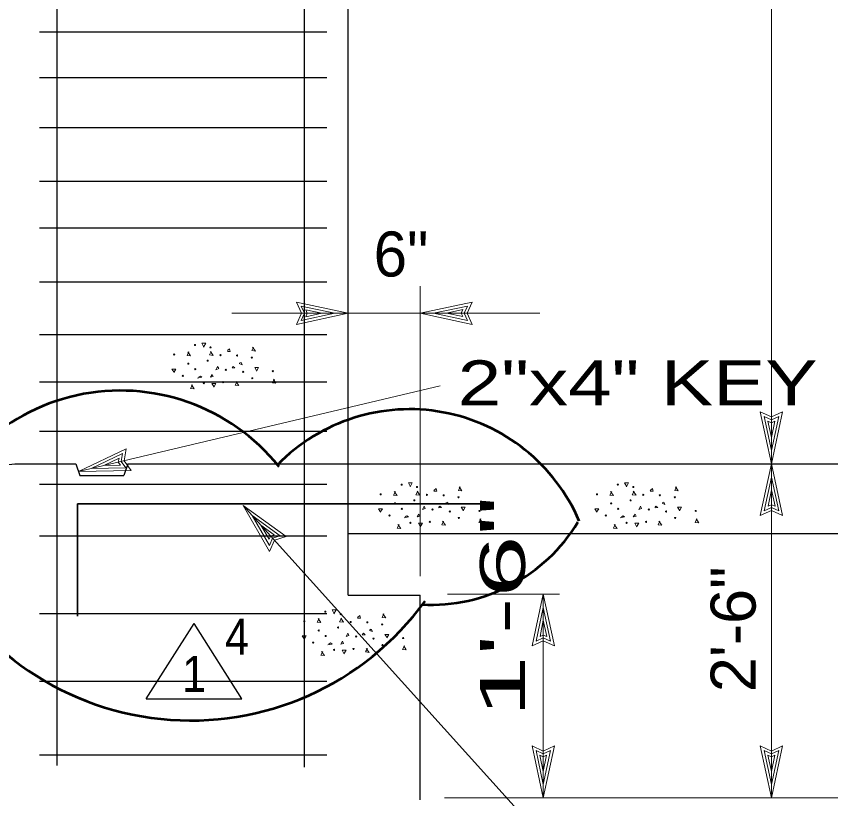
# Model space of a CAD drawing. Extents: x -28.1 to 13.9, y -16.1 to 13.9.
# Drawn here: x -2.228 to 0.036, y 3.076 to 5.249 of the extents above; entities that cross this region are included whole.
import ezdxf
from ezdxf.enums import TextEntityAlignment as Align

# ---------------------------------------------------------------- set-up
doc = ezdxf.new("R2010")
doc.units = 0
doc.header["$LTSCALE"] = 0.05
doc.layers.add('1', color=7, linetype='Continuous', lineweight=13)
doc.layers.add('2', color=7, linetype='Continuous', lineweight=13)

msp = doc.modelspace()

# ---------------------------------------------------------------- linework, layer by layer
at = {"layer": '1', "lineweight": 25}
for p, q in [((-1.30504, 3.64169), (-1.30504, 10.57569)), ((-1.42704, 3.16369), (-1.42704, 10.52469)), ((-2.11404, 3.16869), (-2.11404, 10.51569)), ((-2.16304, 5.20669), (-1.36504, 5.20669)), ((-2.16304, 5.07969), (-1.36504, 5.07969)), ((-2.16304, 4.94069), (-1.36504, 4.94069)), ((-2.16304, 4.79169), (-1.36504, 4.79169)), ((-2.16304, 4.66169), (-1.36504, 4.66169)), ((-2.16304, 4.51169), (-1.36504, 4.51169)), ((-2.16304, 4.36569), (-1.36504, 4.36569)), ((-2.16304, 4.23369), (-1.36504, 4.23369)), ((-2.16304, 4.09669), (-1.36504, 4.09669)), ((-2.06204, 4.00669), (-2.05104, 3.97369)), ((-1.91804, 4.00669), (-1.92904, 3.97369)), ((-1.91804, 4.00669), (0.45096, 4.00669)), ((-2.05104, 3.97369), (-1.92904, 3.97369)), ((-2.16304, 3.94969), (-1.36504, 3.94969)), ((-2.16304, 3.80669), (-1.36504, 3.80669)), ((-1.30504, 3.81269), (0.45596, 3.81269)), ((-1.30504, 3.64169), (-1.10504, 3.64169)), ((-1.10504, 3.07269), (-1.10504, 3.64169)), ((-2.16304, 3.59069), (-1.36504, 3.59069)), ((-1.86643, 3.35403), (-1.73343, 3.56303)), ((-1.60043, 3.35403), (-1.73343, 3.56303)), ((-2.16304, 3.40269), (-1.36504, 3.40269)), ((-1.86643, 3.35403), (-1.60043, 3.35403)), ((-2.16304, 3.19769), (-1.36504, 3.19769))]:
    msp.add_line(p, q, dxfattribs=at)
at = {"layer": '1'}
for p, q in [((-1.10504, 3.69469), (-1.10504, 4.49969)), ((-1.30504, 4.42469), (-1.44904, 4.45569)), ((-1.34204, 4.42469), (-1.43604, 4.44469)), ((-1.42704, 4.42469), (-1.43604, 4.44469)), ((-1.10504, 4.42469), (-0.96104, 4.45569)), ((-1.06804, 4.42469), (-0.97404, 4.44469)), ((-0.97404, 4.44469), (-0.98304, 4.42469)), ((-1.30504, 4.42469), (-1.44904, 4.39369)), ((-1.34204, 4.42469), (-1.43604, 4.40469)), ((-1.43604, 4.40469), (-1.42704, 4.42469)), ((-1.37804, 4.42469), (-1.42304, 4.43369)), ((-1.41904, 4.42469), (-1.42304, 4.43369)), ((-1.37804, 4.42469), (-1.42304, 4.41469)), ((-1.42304, 4.41469), (-1.41904, 4.42469)), ((-1.10504, 4.42469), (-0.96104, 4.39369)), ((-1.06804, 4.42469), (-0.97404, 4.40469)), ((-1.03204, 4.42469), (-0.98704, 4.43469)), ((-1.03204, 4.42469), (-0.98704, 4.41569)), ((-0.98704, 4.43469), (-0.99104, 4.42469)), ((-0.99104, 4.42469), (-0.98704, 4.41569)), ((-0.98304, 4.42469), (-0.97404, 4.40469)), ((-2.05504, 3.98469), (-1.05004, 4.22269)), ((-0.12904, 4.00669), (-0.16004, 4.15069)), ((-0.12904, 4.00669), (-0.09804, 4.15069)), ((-0.12904, 4.04369), (-0.14904, 4.13769)), ((-0.14904, 4.13769), (-0.12904, 4.12869)), ((-0.12904, 4.07969), (-0.13904, 4.12469)), ((-0.13904, 4.12469), (-0.12904, 4.12069)), ((-0.12904, 4.04369), (-0.10904, 4.13769)), ((-0.12904, 4.12869), (-0.10904, 4.13769)), ((-0.12904, 4.07969), (-0.12004, 4.12469)), ((-0.12904, 4.12069), (-0.12004, 4.12469)), ((-2.05504, 3.98469), (-1.92204, 4.04769)), ((-2.01904, 3.99369), (-1.93204, 4.03469)), ((-1.93204, 4.03469), (-1.93604, 4.01269)), ((-1.98404, 4.00169), (-1.94204, 4.02169)), ((-1.94204, 4.02169), (-1.94404, 4.01069)), ((-1.94404, 4.01069), (-1.93804, 4.00269)), ((-1.93604, 4.01269), (-1.92304, 3.99569)), ((-0.12904, 4.00669), (-0.16004, 3.86269)), ((-0.12904, 4.00669), (-0.09804, 3.86269)), ((-2.05504, 3.98469), (-1.90804, 3.98769)), ((-2.01904, 3.99369), (-1.92304, 3.99569)), ((-1.98404, 4.00169), (-1.93804, 4.00269)), ((-0.12904, 3.96969), (-0.14904, 3.87569)), ((-0.12904, 3.96969), (-0.10904, 3.87569)), ((-0.12904, 3.93369), (-0.13804, 3.88869)), ((-0.12904, 3.93369), (-0.11904, 3.88869)), ((-0.12904, 3.89269), (-0.13804, 3.88869)), ((-0.11904, 3.88869), (-0.12904, 3.89269)), ((-1.59712, 3.89047), (-1.47767, 3.80428)), ((-1.59712, 3.89047), (-1.52372, 3.76277)), ((-0.12904, 3.88469), (-0.14904, 3.87569)), ((-0.10904, 3.87569), (-0.12904, 3.88469)), ((-1.57234, 3.86299), (-1.49454, 3.80657)), ((-1.57234, 3.86299), (-1.52425, 3.77979)), ((-1.54824, 3.83625), (-1.52479, 3.79681)), ((-1.54824, 3.83625), (-1.51068, 3.80953)), ((-1.52078, 3.8058), (-1.52479, 3.79681)), ((-1.51068, 3.80953), (-1.52078, 3.8058)), ((-1.49454, 3.80657), (-1.51543, 3.79986)), ((-1.51543, 3.79986), (-1.52425, 3.77979)), ((-1.02904, 3.64469), (-0.71804, 3.64469)), ((-0.76304, 3.64469), (-0.79404, 3.50069)), ((-0.76304, 3.07869), (-0.76304, 3.64469)), ((-0.76304, 3.64469), (-0.73204, 3.50069)), ((-0.76304, 3.60769), (-0.78304, 3.51369)), ((-0.76304, 3.60769), (-0.74304, 3.51369)), ((-0.76304, 3.57169), (-0.77204, 3.52669)), ((-0.76304, 3.57169), (-0.75304, 3.52669)), ((-0.76304, 3.53069), (-0.77204, 3.52669)), ((-0.75304, 3.52669), (-0.76304, 3.53069)), ((-0.76304, 3.52269), (-0.78304, 3.51369)), ((-0.74304, 3.51369), (-0.76304, 3.52269)), ((-0.76304, 3.07869), (-0.79404, 3.22269)), ((-0.76304, 3.07869), (-0.73204, 3.22269)), ((-0.12904, 3.07869), (-0.16004, 3.22269)), ((-0.12904, 3.07869), (-0.09804, 3.22269)), ((-0.76304, 3.11569), (-0.78304, 3.20969)), ((-0.78304, 3.20969), (-0.76304, 3.20069)), ((-0.76304, 3.15169), (-0.77304, 3.19669)), ((-0.77304, 3.19669), (-0.76304, 3.19269)), ((-0.76304, 3.11569), (-0.74304, 3.20969)), ((-0.76304, 3.20069), (-0.74304, 3.20969)), ((-0.76304, 3.15169), (-0.75404, 3.19669)), ((-0.76304, 3.19269), (-0.75404, 3.19669)), ((-0.12904, 3.11569), (-0.14904, 3.20969)), ((-0.14904, 3.20969), (-0.12904, 3.20069)), ((-0.12904, 3.15169), (-0.13904, 3.19669)), ((-0.13904, 3.19669), (-0.12904, 3.19269)), ((-0.12904, 3.11569), (-0.10904, 3.20969)), ((-0.12904, 3.20069), (-0.10904, 3.20969)), ((-0.12904, 3.15169), (-0.12004, 3.19669)), ((-0.12904, 3.19269), (-0.12004, 3.19669)), ((-1.03804, 3.07869), (0.37996, 3.07869))]:
    msp.add_line(p, q, dxfattribs=at)
at = {"layer": '1', "lineweight": 35}
for q in [(-0.90956, 3.89565), (-2.05726, 3.58294)]:
    msp.add_line((-2.05726, 3.89565), q, dxfattribs=at)
at = {"layer": '1'}
for points in [[(-0.12904, 3.07869), (-0.12904, 4.00669), (-0.12904, 10.57569)], [(-1.44904, 4.39369), (-1.43504, 4.42469), (-1.44904, 4.45569)], [(-0.96104, 4.45569), (-0.97504, 4.42469), (-0.96104, 4.39369)], [(-1.62904, 4.42469), (-1.30504, 4.42469), (-1.10504, 4.42469), (-0.77304, 4.42469)], [(-0.16004, 4.15069), (-0.12904, 4.13669), (-0.09804, 4.15069)], [(-1.92204, 4.04769), (-1.92804, 4.01469), (-1.90804, 3.98769)], [(-1.59712, 3.89047), (-0.28558, 2.43598), (0.38318, 2.43322)], [(-0.09804, 3.86269), (-0.12904, 3.87669), (-0.16004, 3.86269)], [(-1.47767, 3.80428), (-1.51007, 3.79393), (-1.52372, 3.76277)], [(-0.73204, 3.50069), (-0.76304, 3.51469), (-0.79404, 3.50069)], [(-0.79404, 3.22269), (-0.76304, 3.20869), (-0.73204, 3.22269)], [(-0.16004, 3.22269), (-0.12904, 3.20869), (-0.09804, 3.22269)]]:
    msp.add_lwpolyline(points, dxfattribs=at)
at = {"layer": '1', "lineweight": 25}
msp.add_lwpolyline([(-2.61504, 3.96269), (-2.23204, 4.00669), (-2.06204, 4.00669)], dxfattribs=at)
at = {"layer": '1', "lineweight": 53}
for centre, radius, start, end in [((-1.93793, 3.64507), 0.56467, 38.72638, 166.28242), ((-1.13461, 3.64489), 0.51309, 23.23358, 135.73917), ((-1.07443, 4.09144), 0.47656, 266.82207, 328.76257), ((-1.74248, 4.09813), 0.80477, 204.09086, 323.98674)]:
    msp.add_arc(centre, radius, start, end, dxfattribs=at)
at = {"layer": '2'}
for p, q in [((-1.64104, 4.32069), (-1.63504, 4.32569)), ((-1.06704, 3.93269), (-1.06104, 3.93769)), ((-0.46604, 3.93269), (-0.46004, 3.93769)), ((-1.27904, 3.57969), (-1.27304, 3.58469))]:
    msp.add_line(p, q, dxfattribs=at)
for points in [[(-1.70704, 4.33269), (-1.71204, 4.34169), (-1.70104, 4.34169), (-1.70704, 4.33069)], [(-1.63504, 4.32569), (-1.63304, 4.31869), (-1.64104, 4.31869)], [(-1.56804, 4.33069), (-1.57304, 4.32069), (-1.56304, 4.31969), (-1.57104, 4.33069)], [(-1.74804, 4.31769), (-1.75304, 4.30769), (-1.74304, 4.30669), (-1.75104, 4.31769)], [(-1.68604, 4.31869), (-1.69104, 4.30869), (-1.68004, 4.30769), (-1.68804, 4.31869)], [(-1.60804, 4.28569), (-1.60304, 4.28769), (-1.60004, 4.28169), (-1.60804, 4.28469)], [(-1.79004, 4.26169), (-1.79504, 4.26969), (-1.78404, 4.26969), (-1.79004, 4.25969)], [(-1.62804, 4.27269), (-1.62504, 4.27669), (-1.62004, 4.27269), (-1.62704, 4.27169)], [(-1.56004, 4.26569), (-1.56504, 4.27369), (-1.55404, 4.27369), (-1.56004, 4.26369)], [(-1.72104, 4.24669), (-1.71604, 4.24969), (-1.71204, 4.24669), (-1.72404, 4.24469)], [(-1.61404, 4.23469), (-1.61904, 4.22469), (-1.60904, 4.22369), (-1.61704, 4.23469)], [(-1.51104, 4.24169), (-1.51604, 4.23169), (-1.50604, 4.23069), (-1.51304, 4.24169)], [(-1.73804, 4.22569), (-1.74304, 4.21569), (-1.73304, 4.21469), (-1.74104, 4.22569)], [(-1.67904, 4.22069), (-1.68404, 4.22969), (-1.67304, 4.22969), (-1.67904, 4.21969)], [(-1.13304, 3.94469), (-1.13804, 3.95369), (-1.12704, 3.95369), (-1.13304, 3.94269)], [(-0.99404, 3.94269), (-0.99904, 3.93269), (-0.98904, 3.93169), (-0.99704, 3.94269)], [(-0.53204, 3.94469), (-0.53704, 3.95369), (-0.52604, 3.95369), (-0.53204, 3.94269)], [(-0.39304, 3.94269), (-0.39804, 3.93269), (-0.38804, 3.93169), (-0.39604, 3.94269)], [(-1.17404, 3.92969), (-1.17904, 3.91969), (-1.16904, 3.91869), (-1.17704, 3.92969)], [(-1.11204, 3.93069), (-1.11704, 3.92069), (-1.10604, 3.91969), (-1.11404, 3.93069)], [(-1.06104, 3.93769), (-1.05904, 3.93069), (-1.06704, 3.93069)], [(-0.57304, 3.92969), (-0.57804, 3.91969), (-0.56804, 3.91869), (-0.57604, 3.92969)], [(-0.51104, 3.93069), (-0.51604, 3.92069), (-0.50504, 3.91969), (-0.51304, 3.93069)], [(-0.46004, 3.93769), (-0.45804, 3.93069), (-0.46604, 3.93069)], [(-1.03404, 3.89769), (-1.02904, 3.89969), (-1.02604, 3.89369), (-1.03404, 3.89669)], [(-0.43304, 3.89769), (-0.42804, 3.89969), (-0.42504, 3.89369), (-0.43304, 3.89669)], [(-1.21604, 3.87369), (-1.22104, 3.88169), (-1.21004, 3.88169), (-1.21604, 3.87169)], [(-1.05404, 3.88469), (-1.05104, 3.88869), (-1.04604, 3.88469), (-1.05304, 3.88369)], [(-0.98604, 3.87769), (-0.99104, 3.88569), (-0.98004, 3.88569), (-0.98604, 3.87569)], [(-0.61504, 3.87369), (-0.62004, 3.88169), (-0.60904, 3.88169), (-0.61504, 3.87169)], [(-0.45304, 3.88469), (-0.45004, 3.88869), (-0.44504, 3.88469), (-0.45204, 3.88369)], [(-0.38504, 3.87769), (-0.39004, 3.88569), (-0.37904, 3.88569), (-0.38504, 3.87569)], [(-1.14704, 3.85869), (-1.14204, 3.86169), (-1.13804, 3.85869), (-1.15004, 3.85669)], [(-0.93704, 3.85369), (-0.94204, 3.84369), (-0.93204, 3.84269), (-0.93904, 3.85369)], [(-0.54604, 3.85869), (-0.54104, 3.86169), (-0.53704, 3.85869), (-0.54904, 3.85669)], [(-0.33604, 3.85369), (-0.34104, 3.84369), (-0.33104, 3.84269), (-0.33804, 3.85369)], [(-1.16404, 3.83769), (-1.16904, 3.82769), (-1.15904, 3.82669), (-1.16704, 3.83769)], [(-1.10504, 3.83269), (-1.11004, 3.84169), (-1.09904, 3.84169), (-1.10504, 3.83169)], [(-1.04004, 3.84669), (-1.04504, 3.83669), (-1.03504, 3.83569), (-1.04304, 3.84669)], [(-0.56304, 3.83769), (-0.56804, 3.82769), (-0.55804, 3.82669), (-0.56604, 3.83769)], [(-0.50404, 3.83269), (-0.50904, 3.84169), (-0.49804, 3.84169), (-0.50404, 3.83169)], [(-0.43904, 3.84669), (-0.44404, 3.83669), (-0.43404, 3.83569), (-0.44204, 3.84669)], [(-1.34504, 3.59169), (-1.35004, 3.60069), (-1.33904, 3.60069), (-1.34504, 3.58969)], [(-1.38604, 3.57669), (-1.39104, 3.56669), (-1.38104, 3.56569), (-1.38904, 3.57669)], [(-1.32404, 3.57769), (-1.32904, 3.56769), (-1.31804, 3.56669), (-1.32604, 3.57769)], [(-1.27304, 3.58469), (-1.27104, 3.57769), (-1.27904, 3.57769)], [(-1.20604, 3.58969), (-1.21104, 3.57969), (-1.20104, 3.57869), (-1.20904, 3.58969)], [(-1.26604, 3.53169), (-1.26304, 3.53569), (-1.25804, 3.53169), (-1.26504, 3.53069)], [(-1.24604, 3.54469), (-1.24104, 3.54669), (-1.23804, 3.54069), (-1.24604, 3.54369)], [(-1.19804, 3.52469), (-1.20304, 3.53269), (-1.19204, 3.53269), (-1.19804, 3.52269)], [(-1.42804, 3.52069), (-1.43304, 3.52869), (-1.42204, 3.52869), (-1.42804, 3.51869)], [(-1.35904, 3.50569), (-1.35404, 3.50869), (-1.35004, 3.50569), (-1.36204, 3.50369)], [(-1.31704, 3.47969), (-1.32204, 3.48869), (-1.31104, 3.48869), (-1.31704, 3.47869)], [(-1.25204, 3.49369), (-1.25704, 3.48369), (-1.24704, 3.48269), (-1.25504, 3.49369)], [(-1.14904, 3.50069), (-1.15404, 3.49069), (-1.14404, 3.48969), (-1.15104, 3.50069)], [(-1.37604, 3.48469), (-1.38104, 3.47469), (-1.37104, 3.47369), (-1.37904, 3.48469)]]:
    msp.add_lwpolyline(points, dxfattribs=at)
for points in [[(-1.68804, 4.24669), (-1.68304, 4.25469), (-1.68004, 4.24869)], [(-1.67304, 4.26769), (-1.66804, 4.27669), (-1.66504, 4.27069)], [(-1.09904, 3.87969), (-1.09404, 3.88869), (-1.09104, 3.88269)], [(-0.49804, 3.87969), (-0.49304, 3.88869), (-0.49004, 3.88269)], [(-1.11404, 3.85869), (-1.10904, 3.86669), (-1.10604, 3.86069)], [(-0.51304, 3.85869), (-0.50804, 3.86669), (-0.50504, 3.86069)], [(-1.31104, 3.52669), (-1.30604, 3.53569), (-1.30304, 3.52969)], [(-1.32604, 3.50569), (-1.32104, 3.51369), (-1.31804, 3.50769)]]:
    msp.add_lwpolyline(points, close=True, dxfattribs=at)
for centre in [(-1.73079, 4.33656), (-1.68804, 4.32981), (-1.78904, 4.30981), (-1.66029, 4.30806), (-1.61404, 4.30706), (-1.57279, 4.30131), (-1.74929, 4.28456), (-1.69554, 4.29281), (-1.73004, 4.26931), (-1.64504, 4.26756), (-1.59704, 4.26181), (-1.51454, 4.26356), (-1.76454, 4.25081), (-1.70654, 4.23056), (-1.65254, 4.23306), (-1.57179, 4.24406), (-1.15679, 3.94856), (-1.11404, 3.94181), (-0.55579, 3.94856), (-0.51304, 3.94181), (-1.21504, 3.92181), (-1.08629, 3.92006), (-1.04004, 3.91906), (-0.61404, 3.92181), (-0.48529, 3.92006), (-0.43904, 3.91906), (-1.17529, 3.89656), (-1.12154, 3.90481), (-0.99879, 3.91331), (-0.57429, 3.89656), (-0.52054, 3.90481), (-0.39779, 3.91331), (-1.15604, 3.88131), (-1.07104, 3.87956), (-1.02304, 3.87381), (-0.94054, 3.87556), (-0.55504, 3.88131), (-0.47004, 3.87956), (-0.42204, 3.87381), (-0.33954, 3.87556), (-1.19054, 3.86281), (-0.99779, 3.85606), (-0.58954, 3.86281), (-0.39679, 3.85606), (-1.13254, 3.84256), (-1.07854, 3.84506), (-0.53154, 3.84256), (-0.47754, 3.84506), (-1.36879, 3.59556), (-1.32604, 3.58881), (-1.42704, 3.56881), (-1.33354, 3.55181), (-1.29829, 3.56706), (-1.25204, 3.56606), (-1.21079, 3.56031), (-1.38729, 3.54356), (-1.40254, 3.50981), (-1.36804, 3.52831), (-1.28304, 3.52656), (-1.23504, 3.52081), (-1.15254, 3.52256), (-1.34454, 3.48956), (-1.29054, 3.49206), (-1.20979, 3.50306)]:
    msp.add_circle(centre, 0.00162, dxfattribs=at)

# ---------------------------------------------------------------- texts
at = {"layer": '1'}
msp.add_text('6"', height=0.125, dxfattribs=at).set_placement((-1.15842, 4.52669), align=Align.CENTER)
at = {"layer": '1', "width": 1.3}
msp.add_text('2"x4" KEY', height=0.125, dxfattribs=at).set_placement((-0.00105, 4.16869), align=Align.RIGHT)
at = {"layer": '1'}
for s, width, p in [('1\'-6"', 1.85, (-0.81404, 3.60932)), ('2\'-6"', 1.05, (-0.17304, 3.54657))]:
    msp.add_text(s, height=0.125, rotation=90, dxfattribs=dict(at, width=width)).set_placement(p, align=Align.CENTER)
at = {"layer": '1', "width": 0.9}
for s, p in [('4', (-1.61409, 3.47603)), ('1', (-1.73309, 3.37303))]:
    msp.add_text(s, height=0.1, dxfattribs=at).set_placement(p, align=Align.CENTER)

doc.saveas('drawing.dxf')
